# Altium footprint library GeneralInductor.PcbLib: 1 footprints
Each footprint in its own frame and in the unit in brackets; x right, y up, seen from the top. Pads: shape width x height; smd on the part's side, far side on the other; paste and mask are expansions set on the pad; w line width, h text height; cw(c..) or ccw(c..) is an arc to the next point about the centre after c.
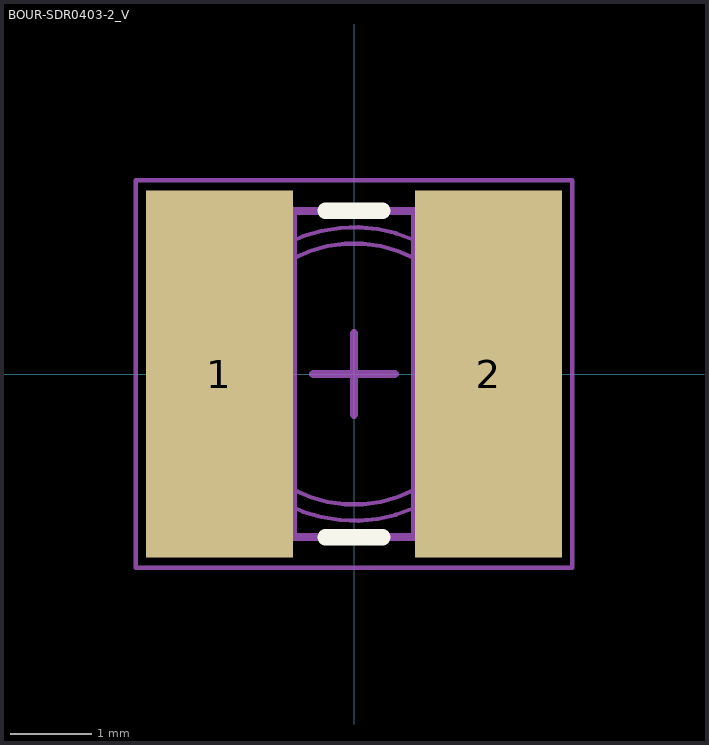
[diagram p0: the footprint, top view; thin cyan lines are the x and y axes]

## BOUR-SDR0403-2_V [mm] "SMD, 2-Leads, Dia 4.5mm, Height 3.5mm"
height 3.5
pads (2):
  rect 1.8x4.5 smd: 1(-1.65,0) 2(1.65,0)
Top Overlay:
  lines w0.2: -0.35,-2 0.35,-2 ; -0.35,2 0.35,2
Mechanical 13:
  circle w0.05: c0,0 r1.6
  circle w0.05: c0,0 r1.8
  lines w0.1: -0.75,-2 0.75,-2 ; -0.75,2 0.75,2 ; 0.75,-2 ccw(c0.167,0) 0.75,2 ; 0.75,-2 0.75,2 ; -0.75,-2 cw(c-0.167,0) -0.75,2 -0.75,-2
Mechanical 15:
  lines w0.05: -2.675,-2.375 -2.675,2.375 2.675,2.375 2.675,-2.375 -2.675,-2.375
  lines w0.1: -0.5,0 0.5,0 ; 0,-0.5 0,0.5
3D body: height 0.75, standoff 0.5, extent -0.75,-2 0.75,2
3D body: height 0.75, standoff 0, extent -2.251,-2 -0.749,2.001
3D body: height 0.75, standoff 0, extent 0.749,-2.001 2.251,2
3D body: height 3, standoff 0.75, extent -1.599,-1.599 1.599,1.599
3D body: height 3.5, standoff 3, extent -2.241,-2.001 2.241,2.001
3D body: height 1.5, standoff 1.25, extent -1.801,-1.801 1.8,0
3D body: height 1, standoff 0.75, extent -1.801,-1.801 1.8,0
3D body: height 2.5, standoff 2.25, extent -1.801,-1.801 1.8,0
3D body: height 2, standoff 1.75, extent -1.801,-1.801 1.8,0
3D body: height 3, standoff 2.75, extent -1.801,-1.801 1.8,0
3D body: height 1.5, standoff 1.25, extent -1.8,0 1.801,1.801
3D body: height 1, standoff 0.75, extent -1.8,0 1.801,1.801
3D body: height 2.5, standoff 2.25, extent -1.801,0 1.8,1.801
3D body: height 2, standoff 1.75, extent -1.8,0 1.801,1.801
3D body: height 3, standoff 2.75, extent -1.8,0 1.801,1.801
